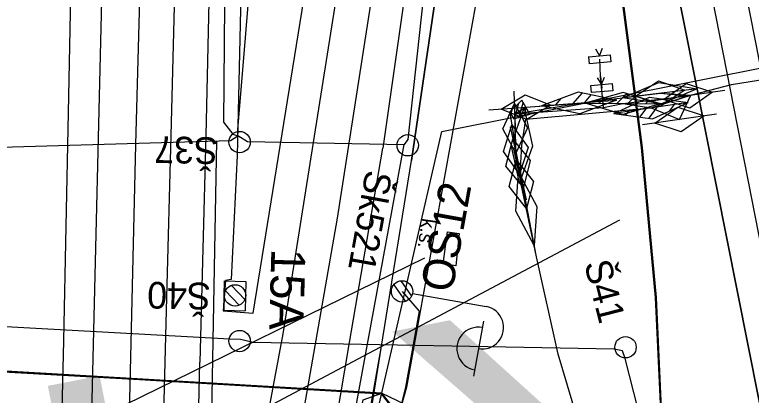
# Model space of a CAD drawing. Extents: x -545736 to -544888, y -1122892 to -1119128.
# Drawn here: x -545127.66 to -545093.16, y -1122420.77 to -1122402.97 of the extents above; entities that cross this region are included whole.
import ezdxf

# ---------------------------------------------------------------- set-up
doc = ezdxf.new("R2010")
doc.units = 0
for name, color, linetype in [('osvětlené plochy-hodnota-obrys', 7, 'Continuous'), ('Vrstva 1 - Koleje', 7, 'Continuous'), ('Vrstva 11 - Trakce', 7, 'Continuous'), ('Vrstva 12 - Trakce zaklady', 7, 'Continuous'), ('Vrstva 25', 7, 'Continuous'), ('Vrstva 26', 7, 'Continuous'), ('Vrstva 27', 7, 'Continuous'), ('Vrstva 28 - zabzar', 7, 'Continuous'), ('Vrstva 31', 7, 'Continuous'), ('Vrstva 32', 7, 'Continuous'), ('Vrstva 33 - prvky sdelzar', 7, 'Continuous'), ('Vrstva 35', 7, 'Continuous'), ('Vrstva 36', 7, 'Continuous'), ('Vrstva 4 - Teren - stezky - prechody - plochy', 7, 'Continuous'), ('Vrstva 43', 7, 'Continuous'), ('Vrstva 44', 7, 'Continuous'), ('Vrstva 63', 7, 'Continuous')]:
    doc.layers.add(name, color=color, linetype=linetype)

msp = doc.modelspace()

# ---------------------------------------------------------------- linework, layer by layer
at = {"layer": 'osvětlené plochy-hodnota-obrys'}
msp.add_lwpolyline([(-545136.491, -1122623.942), (-545134.432, -1122610.076), (-545134.432, -1122610.076), (-545130.588, -1122580.54), (-545121.507, -1122539.928), (-545114.985, -1122440.379), (-545107.655, -1122408.436), (-545092.05, -1122405.326)], dxfattribs=at)
at = {"layer": 'Vrstva 1 - Koleje'}
for points in [[(-545109.24, -1122311.657), (-545109.159, -1122312.443), (-545107.948, -1122324.202), (-545105.285, -1122340.012), (-545104.844, -1122342.604), (-545104.106, -1122346.835), (-545102.665, -1122354.441), (-545101.034, -1122362.799), (-545100.615, -1122364.956), (-545100.274, -1122366.713), (-545099.584, -1122370.264), (-545098.087, -1122377.955), (-545096.662, -1122385.274), (-545095.115, -1122393.214), (-545094.389, -1122396.959), (-545092.81, -1122405.067), (-545091.854, -1122409.976), (-545091.673, -1122410.905), (-545090.872, -1122415.011)], [(-545107.347, -1122342.809), (-545107.32, -1122344.439), (-545107.291, -1122352.482), (-545107.464, -1122361.507), (-545107.673, -1122366.436), (-545107.823, -1122369.959), (-545108.517, -1122380.226), (-545109.517, -1122390.705), (-545110.907, -1122401.845), (-545112.555, -1122412.49), (-545114.203, -1122421.939), (-545115.273, -1122428.098), (-545115.497, -1122429.386), (-545117.305, -1122440.779), (-545118.739, -1122451.202), (-545119.868, -1122460.623), (-545119.896, -1122460.856), (-545122.134, -1122479.934), (-545122.227, -1122480.729)], [(-545122.227, -1122480.729), (-545122.206, -1122479.929), (-545121.705, -1122460.733), (-545121.457, -1122451.242), (-545121.209, -1122441.917), (-545121.14, -1122439.276), (-545121.052, -1122435.9), (-545121.021, -1122434.716), (-545120.822, -1122427.079), (-545120.538, -1122416.197), (-545120.339, -1122408.612), (-545120.039, -1122397.109), (-545119.737, -1122384.601), (-545119.658, -1122373.591), (-545119.757, -1122363.811)], [(-545124.929, -1122395.843), (-545125.151, -1122407.535), (-545125.374, -1122418.205), (-545125.591, -1122427.418), (-545125.847, -1122437.769), (-545125.869, -1122438.447), (-545125.885, -1122439.151), (-545126.109, -1122447.564), (-545126.386, -1122458.223), (-545126.659, -1122468.582), (-545126.947, -1122479.462), (-545127.148, -1122487.159), (-545127.344, -1122494.655), (-545127.587, -1122503.865), (-545127.83, -1122512.852), (-545128.33, -1122532.079), (-545128.351, -1122532.879)]]:
    msp.add_lwpolyline(points, dxfattribs=at)
at = {"layer": 'Vrstva 11 - Trakce'}
for p, q in [((-545117.508, -1122415.635), (-545116.879, -1122416.298)), ((-545117.784, -1122415.888), (-545117.147, -1122416.56))]:
    msp.add_line(p, q, dxfattribs=at)
msp.add_circle((-545117.336, -1122416.101), 0.5, dxfattribs=at)
at = {"layer": 'Vrstva 12 - Trakce zaklady'}
for p, q in [((-545117.826, -1122415.424), (-545116.826, -1122415.451)), ((-545116.826, -1122415.451), (-545116.863, -1122416.823)), ((-545116.826, -1122415.451), (-545116.863, -1122416.823)), ((-545117.863, -1122416.796), (-545116.863, -1122416.823))]:
    msp.add_line(p, q, dxfattribs=at)
for points in [[(-545117.826, -1122415.424), (-545117.826, -1122415.424), (-545117.863, -1122416.796), (-545117.863, -1122416.796), (-545117.826, -1122415.424)], [(-545117.826, -1122415.424), (-545116.826, -1122415.451), (-545116.826, -1122415.451)], [(-545117.863, -1122416.796), (-545116.863, -1122416.823), (-545116.863, -1122416.823)]]:
    msp.add_lwpolyline(points, dxfattribs=at)
at = {"layer": 'Vrstva 25'}
for p, q in [((-545109.905, -1122415.601), (-545109.358, -1122416.388)), ((-545109.576, -1122415.418), (-545109.074, -1122416.14)), ((-545109.025, -1122416.003), (-545105.58, -1122416.623)), ((-545105.704, -1122417.312), (-545106.165, -1122419.871))]:
    msp.add_line(p, q, dxfattribs=at)
msp.add_circle((-545109.517, -1122415.914), 0.5, dxfattribs=at)
msp.add_circle((-545109.517, -1122415.914), 0.5, dxfattribs=at)
for centre, start, end in [((-545105.758, -1122417.607), 259.7886, 79.7886), ((-545105.947, -1122418.589), 79.086, 260.4911)]:
    msp.add_arc(centre, 1, start, end, dxfattribs=at)
at = {"layer": 'Vrstva 26'}
for points in [[(-545114.815, -1122366.586), (-545114.876, -1122368.763), (-545116.01, -1122374.663), (-545115.494, -1122384.043), (-545114.559, -1122390.621), (-545113.865, -1122392.701), (-545112.798, -1122392.81), (-545106.367, -1122395.346), (-545105.682, -1122396.829), (-545105.659, -1122400.159), (-545109.304, -1122420.397), (-545109.666, -1122421.678)], [(-545109.517, -1122415.914), (-545108.712, -1122416.833), (-545109.354, -1122420.397), (-545109.667, -1122421.677), (-545110.467, -1122420.677)], [(-545113.588, -1122440.459), (-545114.2, -1122440.77), (-545115.03, -1122440.61), (-545114.46, -1122437.51), (-545112.75, -1122436.04), (-545114.11, -1122435.24), (-545111.34, -1122420.98), (-545110.467, -1122420.677), (-545135.537, -1122419.205), (-545135.677, -1122419.251), (-545136.659, -1122419.093)]]:
    msp.add_lwpolyline(points, dxfattribs=at)
at = {"layer": 'Vrstva 27'}
for p, q in [((-545100.763, -1122404.932), (-545100.76, -1122404.928)), ((-545100.673, -1122406.282), (-545100.67, -1122406.278))]:
    msp.add_line(p, q, dxfattribs=at)
for points in [[(-545100.461, -1122404.567), (-545100.265, -1122404.884), (-545100.129, -1122404.537)], [(-545100.371, -1122405.917), (-545100.175, -1122406.234), (-545100.039, -1122405.887)]]:
    msp.add_lwpolyline(points, dxfattribs=at)
for points in [[(-545100.763, -1122404.929), (-545099.767, -1122404.839), (-545099.737, -1122405.171), (-545100.733, -1122405.261)], [(-545100.673, -1122406.279), (-545099.677, -1122406.189), (-545099.647, -1122406.521), (-545100.643, -1122406.611)]]:
    msp.add_lwpolyline(points, close=True, dxfattribs=at)
at = {"layer": 'Vrstva 28 - zabzar'}
for p, q in [((-545100.22, -1122405.85), (-545100.16, -1122406.4)), ((-545098.585, -1122406.78), (-545097.5, -1122406.062)), ((-545097.5, -1122406.062), (-545096.275, -1122406.5)), ((-545097.271, -1122406.928), (-545096.204, -1122406.184)), ((-545096.204, -1122406.184), (-545094.969, -1122406.592)), ((-545104.87, -1122407.378), (-545103.754, -1122406.71)), ((-545104.273, -1122406.535), (-545104.167, -1122410.025)), ((-545103.754, -1122406.71), (-545102.55, -1122407.202)), ((-545095.697, -1122406.43), (-545099.163, -1122406.85)), ((-545094.393, -1122406.509), (-545097.847, -1122407.011)), ((-545096.275, -1122406.5), (-545097.36, -1122407.218)), ((-545094.969, -1122406.592), (-545096.036, -1122407.336)), ((-545097.36, -1122407.218), (-545098.585, -1122406.78)), ((-545096.036, -1122407.336), (-545097.271, -1122406.928)), ((-545105.451, -1122407.421), (-545101.969, -1122407.159)), ((-545103.666, -1122407.87), (-545104.87, -1122407.378)), ((-545104.802, -1122408.298), (-545104.255, -1122407.117)), ((-545104.255, -1122407.117), (-545103.638, -1122408.262)), ((-545102.55, -1122407.202), (-545103.666, -1122407.87)), ((-545097.671, -1122408.038), (-545096.604, -1122407.294)), ((-545096.604, -1122407.294), (-545095.369, -1122407.702)), ((-545104.467, -1122407.547), (-545103.913, -1122410.993)), ((-545094.793, -1122407.619), (-545098.247, -1122408.121)), ((-545095.369, -1122407.702), (-545096.436, -1122408.446)), ((-545104.765, -1122409.362), (-545104.374, -1122408.121)), ((-545104.374, -1122408.121), (-545103.615, -1122409.178)), ((-545096.436, -1122408.446), (-545097.671, -1122408.038)), ((-545104.185, -1122409.443), (-545104.802, -1122408.298)), ((-545104.457, -1122408.216), (-545103.703, -1122411.624)), ((-545103.638, -1122408.262), (-545104.185, -1122409.443)), ((-545104.648, -1122410.046), (-545104.331, -1122408.784)), ((-545104.331, -1122408.784), (-545103.512, -1122409.794)), ((-545104.006, -1122410.419), (-545104.765, -1122409.362)), ((-545103.566, -1122412.597), (-545104.294, -1122409.183)), ((-545103.615, -1122409.178), (-545104.006, -1122410.419)), ((-545104.499, -1122411.011), (-545104.173, -1122409.752)), ((-545104.173, -1122409.752), (-545103.361, -1122410.769)), ((-545103.512, -1122409.794), (-545103.829, -1122411.056)), ((-545103.829, -1122411.056), (-545104.648, -1122410.046)), ((-545103.361, -1122410.769), (-545103.687, -1122412.028)), ((-545103.687, -1122412.028), (-545104.499, -1122411.011))]:
    msp.add_line(p, q, dxfattribs=at)
for points in [[(-545095.98, -1122406.73), (-545094.09, -1122406.23), (-545085.61, -1122404.88), (-545075.19, -1122403.13), (-545078.57, -1122384.82), (-545080.03, -1122378.7), (-545078.63, -1122376.44), (-545078.73, -1122374.54), (-545080.88, -1122364.73), (-545082.7, -1122354.07), (-545083.77, -1122348.32), (-545086.63, -1122333.57), (-545090.57, -1122312.4), (-545090.59, -1122308.19), (-545090.62, -1122301.79), (-545090.63, -1122299.65)], [(-545100.08, -1122407.31), (-545100.22, -1122405.85), (-545100.25, -1122405.05)], [(-545103.93, -1122410.89), (-545104.08, -1122409.92), (-545104.19, -1122409.27), (-545104.22, -1122408.28), (-545104.21, -1122407.6), (-545103.71, -1122407.29), (-545101.22, -1122407.1), (-545097.43, -1122406.64), (-545095.98, -1122406.73)], [(-545104.21, -1122407.6), (-545100.08, -1122407.31), (-545099.17, -1122407.12), (-545096.12, -1122406.76), (-545095.98, -1122406.73)], [(-545103.93, -1122410.89), (-545103.95, -1122409.89), (-545103.9, -1122409.08), (-545103.72, -1122407.85), (-545097.85, -1122407.33), (-545096.52, -1122407.87), (-545095.98, -1122406.73)], [(-545081.29, -1122506.35), (-545083.52, -1122495.4), (-545087.27, -1122480.36), (-545088, -1122477.28), (-545088.6, -1122473.44), (-545088.68, -1122470.8), (-545089.31, -1122466.23), (-545090.2, -1122459.67), (-545092.23, -1122451.16), (-545094.2, -1122440.96), (-545096.89, -1122439.25), (-545098.21, -1122435.16), (-545098.87, -1122433.13), (-545100.24, -1122425.44), (-545102.2, -1122418.85), (-545103.21, -1122414.3), (-545103.69, -1122412.05), (-545103.93, -1122410.89)]]:
    msp.add_lwpolyline(points, dxfattribs=at)
at = {"layer": 'Vrstva 31'}
for p, q in [((-545103.904, -1122406.967), (-545104.467, -1122407.503)), ((-545104.022, -1122407.758), (-545103.837, -1122407.086)), ((-545103.533, -1122407.623), (-545103.904, -1122406.967)), ((-545104.402, -1122407.619), (-545104.335, -1122407.376)), ((-545104.249, -1122407.821), (-545104.051, -1122407.106)), ((-545103.798, -1122407.697), (-545103.697, -1122407.333)), ((-545104.467, -1122407.503), (-545104.282, -1122407.83)), ((-545104.282, -1122407.83), (-545103.533, -1122407.623)), ((-545103.571, -1122407.634), (-545103.557, -1122407.581))]:
    msp.add_line(p, q, dxfattribs=at)
for points in [[(-545095.98, -1122406.73), (-545094.09, -1122406.23), (-545085.61, -1122404.88), (-545075.19, -1122403.13), (-545078.57, -1122384.82), (-545080.03, -1122378.7), (-545078.63, -1122376.44), (-545078.73, -1122374.54), (-545080.88, -1122364.73), (-545082.7, -1122354.07), (-545083.77, -1122348.32), (-545086.63, -1122333.57), (-545090.57, -1122312.4), (-545090.59, -1122308.19), (-545090.62, -1122301.79), (-545090.63, -1122299.65), (-545090.83, -1122293.64)], [(-545099.42, -1122398.8), (-545099.19, -1122402.115), (-545098.263, -1122409.178), (-545097.613, -1122416.204), (-545097.239, -1122424.494)], [(-545099.24, -1122402.115), (-545098.313, -1122409.178), (-545097.663, -1122416.204), (-545097.274, -1122424.459), (-545098.365, -1122424.645), (-545100.628, -1122425.068), (-545101.138, -1122425.054), (-545109.701, -1122421.713), (-545110.467, -1122420.727), (-545135.568, -1122419.245), (-545136.694, -1122419.128), (-545149.766, -1122414.21), (-545156.339, -1122413.66), (-545156.372, -1122414.724)], [(-545103.93, -1122410.89), (-545104.19, -1122409.27), (-545104.21, -1122407.6), (-545104.01, -1122407.46), (-545103.71, -1122407.29), (-545101.22, -1122407.1), (-545097.43, -1122406.64), (-545095.98, -1122406.73)], [(-545098.21, -1122435.16), (-545098.87, -1122433.13), (-545100.24, -1122425.44), (-545102.2, -1122418.85), (-545103.21, -1122414.3), (-545103.69, -1122412.05), (-545103.93, -1122410.89), (-545103.95, -1122409.89), (-545103.9, -1122409.08), (-545103.72, -1122407.85), (-545097.85, -1122407.33), (-545095.98, -1122406.73)], [(-545103.792, -1122407.333), (-545103.401, -1122409.111), (-545104.008, -1122410.827), (-545104.399, -1122409.049), (-545103.792, -1122407.333)], [(-545104.055, -1122410.339), (-545103.201, -1122411.946), (-545103.325, -1122413.761), (-545104.179, -1122412.154), (-545104.055, -1122410.339)], [(-545104.055, -1122410.339), (-545103.201, -1122411.946), (-545103.325, -1122413.761), (-545104.179, -1122412.154), (-545104.055, -1122410.339)], [(-545137.56, -1122435.33), (-545137.52, -1122434.99), (-545137.46, -1122434.53), (-545137.32, -1122434.5), (-545135.49, -1122434.13), (-545132.82, -1122434.54), (-545131.67, -1122434.76), (-545128.2, -1122434.85), (-545124.58, -1122434.9), (-545123.28, -1122435.33), (-545115.13, -1122435.9), (-545113.17, -1122435.96), (-545111.79, -1122436.35), (-545107.25, -1122436.01), (-545103.45, -1122435.89), (-545098.21, -1122435.16), (-545098.87, -1122433.13), (-545100.24, -1122425.44), (-545102.2, -1122418.85), (-545103.21, -1122414.3), (-545103.69, -1122412.05)], [(-545156.372, -1122414.724), (-545156.339, -1122413.66), (-545149.766, -1122414.16), (-545149.766, -1122414.16), (-545136.659, -1122419.093), (-545135.677, -1122419.251), (-545110.467, -1122420.677), (-545100.891, -1122425.245), (-545098.365, -1122424.695), (-545097.239, -1122424.494)]]:
    msp.add_lwpolyline(points, dxfattribs=at)
at = {"layer": 'Vrstva 32'}
for p, q in [((-545101.092, -1122406.635), (-545101.511, -1122407.122)), ((-545100.667, -1122406.712), (-545100.985, -1122407.082)), ((-545099.003, -1122406.668), (-545099.461, -1122407.117)), ((-545102.075, -1122406.891), (-545102.325, -1122407.184)), ((-545100.733, -1122407.05), (-545100.787, -1122407.104)), ((-545100.004, -1122406.839), (-545100.278, -1122407.109)), ((-545100.019, -1122406.845), (-545100.169, -1122407.02)), ((-545099.61, -1122406.941), (-545099.661, -1122406.981)), ((-545098.586, -1122406.781), (-545098.934, -1122407.122)), ((-545097.951, -1122406.969), (-545098.116, -1122407.13)), ((-545096.295, -1122407.157), (-545096.25, -1122407.095)), ((-545102.783, -1122407.164), (-545102.832, -1122407.223)), ((-545098.375, -1122407.756), (-545098.083, -1122407.364)), ((-545097.945, -1122407.803), (-545097.562, -1122407.288)), ((-545097.553, -1122407.1), (-545097.607, -1122407.135)), ((-545096.983, -1122407.478), (-545096.753, -1122407.169)), ((-545099.445, -1122407.601), (-545099.397, -1122407.557)), ((-545099.03, -1122407.668), (-545098.893, -1122407.483))]:
    msp.add_line(p, q, dxfattribs=at)
for points in [[(-545097.43, -1122406.64), (-545096.12, -1122406.76), (-545095.98, -1122406.73), (-545094.09, -1122406.23), (-545085.61, -1122404.88), (-545075.19, -1122403.13)], [(-545096.12, -1122406.76), (-545094.09, -1122406.23), (-545085.61, -1122404.88), (-545075.19, -1122403.13)], [(-545099.167, -1122406.852), (-545097.491, -1122406.144), (-545095.693, -1122406.428), (-545097.369, -1122407.136), (-545099.167, -1122406.852)], [(-545128.2, -1122434.85), (-545124.58, -1122434.9), (-545123.28, -1122435.33), (-545119.31, -1122435.79), (-545115.13, -1122435.9), (-545113.17, -1122435.96), (-545107.25, -1122436.01), (-545103.45, -1122435.89), (-545098.21, -1122435.16), (-545098.87, -1122433.13), (-545100.24, -1122425.44), (-545102.2, -1122418.85), (-545103.21, -1122414.3), (-545104.19, -1122409.27), (-545104.21, -1122407.6), (-545101.22, -1122407.1), (-545097.43, -1122406.64)], [(-545128.2, -1122434.85), (-545123.28, -1122435.33), (-545119.31, -1122435.79), (-545115.13, -1122435.9), (-545113.17, -1122435.96), (-545111.79, -1122436.35), (-545107.25, -1122436.01), (-545103.45, -1122435.89), (-545098.21, -1122435.16), (-545098.87, -1122433.13), (-545100.24, -1122425.44), (-545102.2, -1122418.85), (-545103.21, -1122414.3), (-545103.93, -1122410.89), (-545104.19, -1122409.27), (-545104.21, -1122407.6), (-545104.01, -1122407.46), (-545103.71, -1122407.29), (-545101.22, -1122407.1), (-545099.17, -1122407.12), (-545097.85, -1122407.33), (-545096.12, -1122406.76)], [(-545099.463, -1122406.966), (-545101.181, -1122407.608), (-545102.977, -1122407.234)], [(-545099.593, -1122407.586), (-545097.924, -1122406.826), (-545096.107, -1122407.074)], [(-545097.408, -1122407.137), (-545099.175, -1122407.629), (-545100.932, -1122407.103)]]:
    msp.add_lwpolyline(points, dxfattribs=at)
for points in [[(-545099.463, -1122406.966), (-545101.259, -1122406.592), (-545102.977, -1122407.234)], [(-545097.408, -1122407.137), (-545099.165, -1122406.611), (-545100.932, -1122407.103)], [(-545099.593, -1122407.586), (-545097.776, -1122407.834), (-545096.107, -1122407.074)]]:
    msp.add_lwpolyline(points, close=True, dxfattribs=at)
at = {"layer": 'Vrstva 33 - prvky sdelzar'}
for points in [[(-545096.12, -1122406.76), (-545094.09, -1122406.23), (-545085.61, -1122404.88), (-545075.19, -1122403.13)], [(-545110.467, -1122420.727), (-545135.568, -1122419.245)]]:
    msp.add_lwpolyline(points, dxfattribs=at)
at = {"layer": 'Vrstva 35'}
for points in [[(-545096.12, -1122406.76), (-545094.09, -1122406.23), (-545085.61, -1122404.88), (-545075.19, -1122403.13)], [(-545095.98, -1122406.73), (-545094.09, -1122406.23), (-545085.61, -1122404.88)]]:
    msp.add_lwpolyline(points, dxfattribs=at)
at = {"layer": 'Vrstva 36'}
msp.add_lwpolyline([(-545107.587, -1122414.622), (-545107.381, -1122413.119), (-545106.833, -1122413.205), (-545107, -1122414.722)], close=True, dxfattribs=at)
at = {"layer": 'Vrstva 4 - Teren - stezky - prechody - plochy'}
for points in [[(-545100.915, -1122379.805), (-545096.774, -1122401.019), (-545090.332, -1122433.377), (-545090.074, -1122434.757), (-545085.349, -1122459.985), (-545085.015, -1122461.52), (-545081.07, -1122481.884), (-545079.587, -1122481.709), (-545079.247, -1122484.854), (-545076.321, -1122485.056), (-545075.964, -1122483.68), (-545081.755, -1122453.25), (-545091.085, -1122405.745), (-545097.013, -1122374.966), (-545101.617, -1122351.417), (-545104.019, -1122337.885), (-545106.569, -1122322.088), (-545105.65, -1122321.963), (-545100.125, -1122351.182), (-545095.522, -1122374.321), (-545089.503, -1122405.512), (-545080.247, -1122452.974), (-545074.197, -1122483.96)], [(-545079.587, -1122481.709), (-545083.734, -1122459.587), (-545088.622, -1122434.525), (-545095.308, -1122400.508), (-545099.066, -1122380.894), (-545103.569, -1122357.921), (-545104.718, -1122351.085), (-545105.693, -1122351.143), (-545105.904, -1122359.937), (-545106.198, -1122369.165), (-545107.396, -1122385.739), (-545107.881, -1122390.846), (-545108.53, -1122396.005), (-545110.419, -1122409.211)], [(-545125.7, -1122490.242), (-545124.874, -1122490.272), (-545123.644, -1122473.006), (-545123.016, -1122448.972), (-545122.731, -1122437.064), (-545123.936, -1122436.879), (-545123.869, -1122434.874), (-545122.602, -1122434.898), (-545121.99, -1122409.031), (-545121.443, -1122389.244), (-545121.276, -1122374.996), (-545121.396, -1122364.457)], [(-545125.7, -1122490.242), (-545125.396, -1122473.121), (-545124.781, -1122448.925), (-545124.353, -1122434.513), (-545123.741, -1122408.723), (-545123.267, -1122389.415), (-545123.323, -1122374.79), (-545123.517, -1122364.601)], [(-545079.587, -1122481.709), (-545081.07, -1122481.884), (-545085.015, -1122461.52), (-545085.349, -1122459.985), (-545090.074, -1122434.757), (-545090.332, -1122433.377), (-545096.774, -1122401.019), (-545100.641, -1122381.169), (-545100.915, -1122379.805), (-545103.919, -1122364.365), (-545104.378, -1122364.37), (-545105.142, -1122376.501), (-545105.945, -1122385.58), (-545106.432, -1122389.825), (-545107.117, -1122396.527), (-545109.066, -1122409.783)], [(-545118.073, -1122366.062), (-545118.209, -1122386.317), (-545118.707, -1122408.623), (-545118.989, -1122419.225)], [(-545116.693, -1122366.257), (-545116.703, -1122386.279), (-545117.244, -1122409.555), (-545117.527, -1122415.354), (-545117.792, -1122415.406), (-545117.894, -1122416.818), (-545116.495, -1122416.931), (-545114.124, -1122402.252), (-545112.935, -1122392.795), (-545112.107, -1122386.756)], [(-545112.107, -1122386.756), (-545112.848, -1122386.657), (-545115.797, -1122386.153), (-545116.703, -1122386.279), (-545117.244, -1122409.555), (-545117.527, -1122415.354), (-545117.792, -1122415.406), (-545117.894, -1122416.818), (-545116.495, -1122416.931), (-545114.124, -1122402.252), (-545112.107, -1122386.756)], [(-545119.648, -1122440.783), (-545118.813, -1122440.815), (-545117.071, -1122428.871), (-545118.272, -1122428.69), (-545117.905, -1122426.651), (-545116.751, -1122426.83), (-545115.092, -1122417.897), (-545112.607, -1122402.237), (-545111.452, -1122393.454), (-545110.797, -1122386.704)], [(-545120.045, -1122519.696), (-545119.214, -1122493.259), (-545118.634, -1122481.752), (-545118.777, -1122481.581), (-545118.722, -1122480.14), (-545118.476, -1122479.975), (-545117.897, -1122471.45), (-545115.344, -1122450.576), (-545115.387, -1122450.032), (-545115.234, -1122448.677), (-545115.069, -1122448.275), (-545112.694, -1122432.425), (-545110.499, -1122418.57), (-545109.066, -1122409.783), (-545107.117, -1122396.527)], [(-545122.072, -1122537.394), (-545121.662, -1122521.852), (-545120.987, -1122493.144), (-545120.221, -1122493.122), (-545120.1, -1122491.103), (-545120.938, -1122491.007), (-545120.447, -1122482.376), (-545119.776, -1122482.368), (-545119.577, -1122479.361), (-545120.237, -1122479.324), (-545119.457, -1122470.075), (-545118.588, -1122470.091), (-545118.509, -1122468.05), (-545119.197, -1122468.005), (-545114.315, -1122432.177), (-545111.982, -1122418.3), (-545110.419, -1122409.211)], [(-545122.072, -1122537.394), (-545120.802, -1122537.422), (-545120.268, -1122521.539), (-545120.287, -1122519.886), (-545119.399, -1122493.188), (-545118.777, -1122481.581), (-545118.722, -1122480.14), (-545117.685, -1122467.891), (-545115.387, -1122450.032), (-545115.234, -1122448.677), (-545112.928, -1122432.259), (-545110.499, -1122418.57), (-545109.066, -1122409.783)], [(-545115.234, -1122448.677), (-545112.928, -1122432.259), (-545110.499, -1122418.57)], [(-545119.648, -1122440.783), (-545119.154, -1122426.809), (-545118.989, -1122419.225)]]:
    msp.add_lwpolyline(points, dxfattribs=at)
at = {"layer": 'Vrstva 43'}
for centre in [(-545117.128, -1122408.927), (-545109.25, -1122409.075), (-545117.128, -1122418.234), (-545099.048, -1122418.526)]:
    msp.add_circle(centre, 0.5, dxfattribs=at)
at = {"layer": 'Vrstva 44'}
for points in [[(-545104.957, -1122355.747), (-545106.381, -1122382.598), (-545109.241, -1122408.812), (-545109.415, -1122409.043), (-545109.421, -1122409.06), (-545116.758, -1122408.911), (-545117.209, -1122408.632)], [(-545117.51, -1122363.842), (-545117.874, -1122407.999), (-545117.44, -1122408.548), (-545117.209, -1122408.632)], [(-545161.563, -1122409.448), (-545161.04, -1122409.449), (-545159.873, -1122409.474), (-545158.718, -1122409.518), (-545157.567, -1122409.551), (-545155.535, -1122409.595), (-545151.035, -1122409.842), (-545150.699, -1122409.811), (-545150.354, -1122409.803), (-545117.558, -1122408.854), (-545117.209, -1122408.632), (-545117.207, -1122408.356), (-545114.472, -1122375.479)], [(-545133.427, -1122599.241), (-545132.083, -1122579.16), (-545130.845, -1122531.562), (-545130.119, -1122502.202), (-545130.021, -1122501.998), (-545129.768, -1122502.059), (-545120.639, -1122502.325), (-545120.437, -1122502.27), (-545120.505, -1122501.979), (-545119.331, -1122472.539), (-545116.186, -1122445.902), (-545109.415, -1122409.043)], [(-545118.58, -1122430.14), (-545118.188, -1122408.872)], [(-545053.287, -1122633.279), (-545063.238, -1122586.146), (-545063.248, -1122585.919), (-545063.296, -1122585.762), (-545072.411, -1122534.849), (-545072.406, -1122534.601), (-545072.52, -1122534.494), (-545080.043, -1122501.027), (-545080.093, -1122500.849), (-545080.193, -1122500.397), (-545087.505, -1122464.21), (-545087.659, -1122463.509), (-545087.757, -1122463.363), (-545099.069, -1122419.052), (-545099.193, -1122418.695), (-545099.586, -1122418.621), (-545116.487, -1122418.299), (-545117.079, -1122418.156), (-545117.605, -1122418.155), (-545149.644, -1122416.388), (-545150.026, -1122416.395), (-545150.307, -1122416.258), (-545156.662, -1122416.357)]]:
    msp.add_lwpolyline(points, dxfattribs=at)
at = {"layer": 'Vrstva 63'}
for p, q in [((-545099.334, -1122412.581), (-545172.254, -1122451.231)), ((-545108.468, -1122414.355), (-545173.267, -1122446.057))]:
    msp.add_line(p, q, dxfattribs=at)

# ---------------------------------------------------------------- texts
at = {"layer": 'osvětlené plochy-hodnota-obrys'}
msp.add_text('10', height=22.7812, rotation=281.0956, dxfattribs=at).set_placement((-545126.555, -1122418.056))
at = {"layer": 'Vrstva 11 - Trakce'}
msp.add_text('15A', height=1.6, rotation=268.4552, dxfattribs=at).set_placement((-545115.636, -1122413.897))
at = {"layer": 'Vrstva 25'}
msp.add_text('OS12', height=1.5, rotation=79.7886, dxfattribs=at).set_placement((-545107.17, -1122416.012))
at = {"layer": 'Vrstva 43'}
for s, rotation, p in [('Š37', 178.8366, (-545118.133, -1122408.709)), ('Šk521', 259.7673, (-545111.203, -1122410.186)), ('Š41', 284.321, (-545100.992, -1122414.606)), ('Š40', 178.9085, (-545118.466, -1122415.515))]:
    msp.add_text(s, height=1.25, rotation=rotation, dxfattribs=at).set_placement(p)
at = {"layer": 'Vrstva 63'}
msp.add_text('k.s.', height=0.6741, rotation=261.7066, dxfattribs=at).set_placement((-545108.584, -1122412.46))
msp.add_text('k.s.', height=0.6741, rotation=261.7066, dxfattribs=at).set_placement((-545108.584, -1122412.46))

doc.saveas('drawing.dxf')
